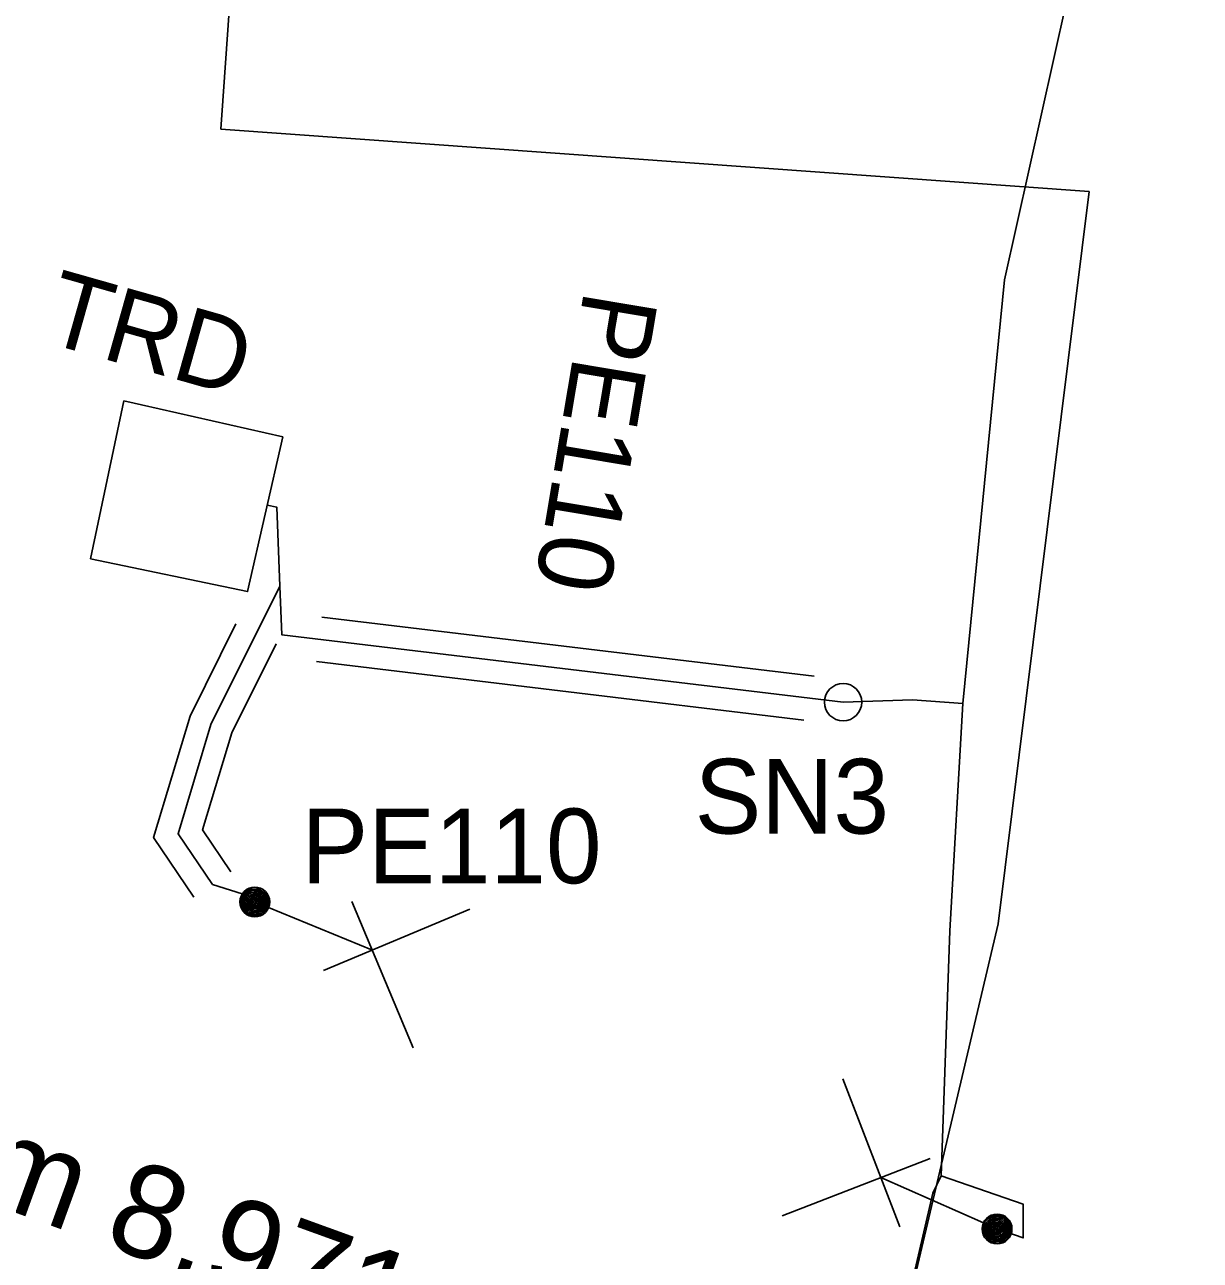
# Model space of a CAD drawing. Extents: x -731967 to -723173, y -945358 to -941505.
# Drawn here: x -725800 to -725784.27, y -942608.48 to -942591.94 of the extents above; entities that cross this region are included whole.
import ezdxf

# ---------------------------------------------------------------- set-up
doc = ezdxf.new("R2010")
doc.units = 0
for name, color, linetype in [('Vrstva 2', 7, 'Continuous'), ('Vrstva 28', 7, 'Continuous'), ('Vrstva 35', 7, 'Continuous')]:
    doc.layers.add(name, color=color, linetype=linetype)

msp = doc.modelspace()

# ---------------------------------------------------------------- linework, layer by layer
at = {"layer": 'Vrstva 2'}
for p, q in [((-725798.677, -942596.977), (-725799.12, -942599.09)), ((-725798.677, -942596.977), (-725799.12, -942599.09)), ((-725798.677, -942596.977), (-725796.55, -942597.46)), ((-725798.677, -942596.977), (-725796.55, -942597.46)), ((-725795.623, -942603.677), (-725794.804, -942605.634)), ((-725795.623, -942603.677), (-725794.804, -942605.634)), ((-725796.738, -942603.76), (-725795.35, -942604.328)), ((-725796.738, -942603.76), (-725795.35, -942604.328)), ((-725796.002, -942604.601), (-725794.045, -942603.781)), ((-725796.002, -942604.601), (-725794.045, -942603.781)), ((-725788.289, -942608.031), (-725789.054, -942606.052)), ((-725788.289, -942608.031), (-725789.054, -942606.052)), ((-725787.885, -942607.118), (-725789.864, -942607.883)), ((-725787.885, -942607.118), (-725789.864, -942607.883)), ((-725787.173, -942607.979), (-725788.545, -942607.372)), ((-725787.173, -942607.979), (-725788.545, -942607.372))]:
    msp.add_line(p, q, dxfattribs=at)
for points in [[(-725796.55, -942597.46), (-725797.02, -942599.53), (-725799.12, -942599.09)], [(-725796.55, -942597.46), (-725797.02, -942599.53), (-725799.12, -942599.09)], [(-725789.436, -942600.661), (-725796.025, -942599.872)], [(-725789.436, -942600.661), (-725796.025, -942599.872)], [(-725797.175, -942599.962), (-725797.79, -942601.199), (-725798.278, -942602.82), (-725797.738, -942603.618)], [(-725797.175, -942599.962), (-725797.79, -942601.199), (-725798.278, -942602.82), (-725797.738, -942603.618)], [(-725796.637, -942600.229), (-725797.23, -942601.421), (-725797.622, -942602.72), (-725797.242, -942603.282)], [(-725796.637, -942600.229), (-725797.23, -942601.421), (-725797.622, -942602.72), (-725797.242, -942603.282)], [(-725789.577, -942601.249), (-725796.096, -942600.468)], [(-725789.577, -942601.249), (-725796.096, -942600.468)], [(-725796.847, -942603.499), (-725796.954, -942603.49), (-725797.06, -942603.548), (-725797.11, -942603.651), (-725797.101, -942603.749), (-725797.033, -942603.838), (-725796.923, -942603.874), (-725796.825, -942603.847), (-725796.757, -942603.776), (-725796.737, -942603.664), (-725796.782, -942603.567), (-725796.859, -942603.516), (-725796.963, -942603.512), (-725797.054, -942603.572), (-725797.093, -942603.66), (-725797.08, -942603.751), (-725797.011, -942603.831), (-725796.913, -942603.855), (-725796.831, -942603.829), (-725796.768, -942603.755), (-725796.758, -942603.654), (-725796.8, -942603.574), (-725796.873, -942603.531), (-725796.97, -942603.535), (-725797.046, -942603.593), (-725797.074, -942603.667), (-725797.057, -942603.755), (-725796.989, -942603.82), (-725796.909, -942603.835), (-725796.835, -942603.807), (-725796.782, -942603.735), (-725796.779, -942603.65), (-725796.818, -942603.586), (-725796.889, -942603.548), (-725796.975, -942603.557), (-725797.033, -942603.608), (-725797.055, -942603.675), (-725797.034, -942603.754), (-725796.973, -942603.806), (-725796.907, -942603.815), (-725796.839, -942603.785), (-725796.797, -942603.719), (-725796.801, -942603.65), (-725796.835, -942603.597), (-725796.903, -942603.566), (-725796.973, -942603.579), (-725797.018, -942603.621), (-725797.036, -942603.685), (-725797.011, -942603.752), (-725796.961, -942603.79), (-725796.904, -942603.796), (-725796.845, -942603.765), (-725796.815, -942603.708), (-725796.819, -942603.653), (-725796.854, -942603.605), (-725796.913, -942603.584), (-725796.968, -942603.599), (-725797.005, -942603.635), (-725797.015, -942603.693), (-725796.992, -942603.745), (-725796.952, -942603.773), (-725796.901, -942603.774), (-725796.853, -942603.745), (-725796.833, -942603.7), (-725796.84, -942603.655), (-725796.872, -942603.616), (-725796.92, -942603.604), (-725796.96, -942603.617), (-725796.989, -942603.65), (-725796.996, -942603.698), (-725796.976, -942603.736), (-725796.943, -942603.754), (-725796.9, -942603.754), (-725796.865, -942603.728), (-725796.853, -942603.695), (-725796.859, -942603.658), (-725796.888, -942603.63), (-725796.922, -942603.624), (-725796.953, -942603.635), (-725796.973, -942603.664), (-725796.975, -942603.7), (-725796.959, -942603.723), (-725796.933, -942603.736), (-725796.901, -942603.734), (-725796.879, -942603.715), (-725796.871, -942603.69), (-725796.88, -942603.663), (-725796.901, -942603.646), (-725796.923, -942603.643), (-725796.943, -942603.652), (-725796.957, -942603.674), (-725796.956, -942603.696), (-725796.945, -942603.712), (-725796.926, -942603.718), (-725796.906, -942603.715), (-725796.896, -942603.702), (-725796.891, -942603.686), (-725796.897, -942603.671), (-725796.91, -942603.663), (-725796.922, -942603.663), (-725796.933, -942603.669)], [(-725796.847, -942603.499), (-725796.954, -942603.49), (-725797.06, -942603.548), (-725797.11, -942603.651), (-725797.101, -942603.749), (-725797.033, -942603.838), (-725796.923, -942603.874), (-725796.825, -942603.847), (-725796.757, -942603.776), (-725796.737, -942603.664), (-725796.782, -942603.567), (-725796.859, -942603.516), (-725796.963, -942603.512), (-725797.054, -942603.572), (-725797.093, -942603.66), (-725797.08, -942603.751), (-725797.011, -942603.831), (-725796.913, -942603.855), (-725796.831, -942603.829), (-725796.768, -942603.755), (-725796.758, -942603.654), (-725796.8, -942603.574), (-725796.873, -942603.531), (-725796.97, -942603.535), (-725797.046, -942603.593), (-725797.074, -942603.667), (-725797.057, -942603.755), (-725796.989, -942603.82), (-725796.909, -942603.835), (-725796.835, -942603.807), (-725796.782, -942603.735), (-725796.779, -942603.65), (-725796.818, -942603.586), (-725796.889, -942603.548), (-725796.975, -942603.557), (-725797.033, -942603.608), (-725797.055, -942603.675), (-725797.034, -942603.754), (-725796.973, -942603.806), (-725796.907, -942603.815), (-725796.839, -942603.785), (-725796.797, -942603.719), (-725796.801, -942603.65), (-725796.835, -942603.597), (-725796.903, -942603.566), (-725796.973, -942603.579), (-725797.018, -942603.621), (-725797.036, -942603.685), (-725797.011, -942603.752), (-725796.961, -942603.79), (-725796.904, -942603.796), (-725796.845, -942603.765), (-725796.815, -942603.708), (-725796.819, -942603.653), (-725796.854, -942603.605), (-725796.913, -942603.584), (-725796.968, -942603.599), (-725797.005, -942603.635), (-725797.015, -942603.693), (-725796.992, -942603.745), (-725796.952, -942603.773), (-725796.901, -942603.774), (-725796.853, -942603.745), (-725796.833, -942603.7), (-725796.84, -942603.655), (-725796.872, -942603.616), (-725796.92, -942603.604), (-725796.96, -942603.617), (-725796.989, -942603.65), (-725796.996, -942603.698), (-725796.976, -942603.736), (-725796.943, -942603.754), (-725796.9, -942603.754), (-725796.865, -942603.728), (-725796.853, -942603.695), (-725796.859, -942603.658), (-725796.888, -942603.63), (-725796.922, -942603.624), (-725796.953, -942603.635), (-725796.973, -942603.664), (-725796.975, -942603.7), (-725796.959, -942603.723), (-725796.933, -942603.736), (-725796.901, -942603.734), (-725796.879, -942603.715), (-725796.871, -942603.69), (-725796.88, -942603.663), (-725796.901, -942603.646), (-725796.923, -942603.643), (-725796.943, -942603.652), (-725796.957, -942603.674), (-725796.956, -942603.696), (-725796.945, -942603.712), (-725796.926, -942603.718), (-725796.906, -942603.715), (-725796.896, -942603.702), (-725796.891, -942603.686), (-725796.897, -942603.671), (-725796.91, -942603.663), (-725796.922, -942603.663), (-725796.933, -942603.669)], [(-725796.933, -942603.669), (-725796.938, -942603.68), (-725796.936, -942603.69), (-725796.93, -942603.698), (-725796.921, -942603.7), (-725796.913, -942603.697), (-725796.911, -942603.691), (-725796.91, -942603.685), (-725796.913, -942603.681), (-725796.917, -942603.681)], [(-725796.933, -942603.669), (-725796.938, -942603.68), (-725796.936, -942603.69), (-725796.93, -942603.698), (-725796.921, -942603.7), (-725796.913, -942603.697), (-725796.911, -942603.691), (-725796.91, -942603.685), (-725796.913, -942603.681), (-725796.917, -942603.681)], [(-725787.071, -942608.243), (-725786.965, -942608.255), (-725786.857, -942608.2), (-725786.804, -942608.099), (-725786.81, -942608), (-725786.875, -942607.91), (-725786.985, -942607.87), (-725787.084, -942607.894), (-725787.153, -942607.964), (-725787.177, -942608.075), (-725787.134, -942608.173), (-725787.058, -942608.227), (-725786.955, -942608.233), (-725786.862, -942608.176), (-725786.821, -942608.089), (-725786.831, -942607.997), (-725786.898, -942607.916), (-725786.995, -942607.889), (-725787.078, -942607.913), (-725787.143, -942607.985), (-725787.155, -942608.085), (-725787.116, -942608.166), (-725787.044, -942608.211), (-725786.947, -942608.21), (-725786.87, -942608.155), (-725786.84, -942608.082), (-725786.854, -942607.993), (-725786.92, -942607.926), (-725787, -942607.909), (-725787.075, -942607.935), (-725787.13, -942608.005), (-725787.135, -942608.09), (-725787.098, -942608.156), (-725787.028, -942608.195), (-725786.942, -942608.188), (-725786.882, -942608.14), (-725786.859, -942608.072), (-725786.877, -942607.993), (-725786.937, -942607.939), (-725787.002, -942607.929), (-725787.071, -942607.956), (-725787.115, -942608.021), (-725787.113, -942608.091), (-725787.08, -942608.145), (-725787.014, -942608.178), (-725786.943, -942608.166), (-725786.896, -942608.125), (-725786.877, -942608.062), (-725786.9, -942607.995), (-725786.949, -942607.956), (-725787.006, -942607.948), (-725787.066, -942607.977), (-725787.097, -942608.033), (-725787.094, -942608.088), (-725787.061, -942608.137), (-725787.002, -942608.16), (-725786.947, -942608.147), (-725786.91, -942608.111), (-725786.898, -942608.054), (-725786.919, -942608.001), (-725786.959, -942607.972), (-725787.01, -942607.969), (-725787.058, -942607.997), (-725787.079, -942608.041), (-725787.074, -942608.086), (-725787.043, -942608.126), (-725786.995, -942608.14), (-725786.955, -942608.128), (-725786.925, -942608.095), (-725786.917, -942608.049), (-725786.936, -942608.01), (-725786.968, -942607.991), (-725787.011, -942607.989), (-725787.046, -942608.014), (-725787.06, -942608.047), (-725787.054, -942608.084), (-725787.026, -942608.113), (-725786.993, -942608.12), (-725786.962, -942608.11), (-725786.941, -942608.082), (-725786.938, -942608.046), (-725786.953, -942608.022), (-725786.979, -942608.008), (-725787.01, -942608.009), (-725787.033, -942608.028), (-725787.041, -942608.053), (-725787.034, -942608.08), (-725787.013, -942608.098), (-725786.991, -942608.101), (-725786.971, -942608.093), (-725786.957, -942608.071), (-725786.957, -942608.049), (-725786.967, -942608.033), (-725786.986, -942608.026), (-725787.006, -942608.029), (-725787.017, -942608.042), (-725787.021, -942608.057), (-725787.016, -942608.072), (-725787.003, -942608.08), (-725786.992, -942608.081), (-725786.98, -942608.075)], [(-725787.071, -942608.243), (-725786.965, -942608.255), (-725786.857, -942608.2), (-725786.804, -942608.099), (-725786.81, -942608), (-725786.875, -942607.91), (-725786.985, -942607.87), (-725787.084, -942607.894), (-725787.153, -942607.964), (-725787.177, -942608.075), (-725787.134, -942608.173), (-725787.058, -942608.227), (-725786.955, -942608.233), (-725786.862, -942608.176), (-725786.821, -942608.089), (-725786.831, -942607.997), (-725786.898, -942607.916), (-725786.995, -942607.889), (-725787.078, -942607.913), (-725787.143, -942607.985), (-725787.155, -942608.085), (-725787.116, -942608.166), (-725787.044, -942608.211), (-725786.947, -942608.21), (-725786.87, -942608.155), (-725786.84, -942608.082), (-725786.854, -942607.993), (-725786.92, -942607.926), (-725787, -942607.909), (-725787.075, -942607.935), (-725787.13, -942608.005), (-725787.135, -942608.09), (-725787.098, -942608.156), (-725787.028, -942608.195), (-725786.942, -942608.188), (-725786.882, -942608.14), (-725786.859, -942608.072), (-725786.877, -942607.993), (-725786.937, -942607.939), (-725787.002, -942607.929), (-725787.071, -942607.956), (-725787.115, -942608.021), (-725787.113, -942608.091), (-725787.08, -942608.145), (-725787.014, -942608.178), (-725786.943, -942608.166), (-725786.896, -942608.125), (-725786.877, -942608.062), (-725786.9, -942607.995), (-725786.949, -942607.956), (-725787.006, -942607.948), (-725787.066, -942607.977), (-725787.097, -942608.033), (-725787.094, -942608.088), (-725787.061, -942608.137), (-725787.002, -942608.16), (-725786.947, -942608.147), (-725786.91, -942608.111), (-725786.898, -942608.054), (-725786.919, -942608.001), (-725786.959, -942607.972), (-725787.01, -942607.969), (-725787.058, -942607.997), (-725787.079, -942608.041), (-725787.074, -942608.086), (-725787.043, -942608.126), (-725786.995, -942608.14), (-725786.955, -942608.128), (-725786.925, -942608.095), (-725786.917, -942608.049), (-725786.936, -942608.01), (-725786.968, -942607.991), (-725787.011, -942607.989), (-725787.046, -942608.014), (-725787.06, -942608.047), (-725787.054, -942608.084), (-725787.026, -942608.113), (-725786.993, -942608.12), (-725786.962, -942608.11), (-725786.941, -942608.082), (-725786.938, -942608.046), (-725786.953, -942608.022), (-725786.979, -942608.008), (-725787.01, -942608.009), (-725787.033, -942608.028), (-725787.041, -942608.053), (-725787.034, -942608.08), (-725787.013, -942608.098), (-725786.991, -942608.101), (-725786.971, -942608.093), (-725786.957, -942608.071), (-725786.957, -942608.049), (-725786.967, -942608.033), (-725786.986, -942608.026), (-725787.006, -942608.029), (-725787.017, -942608.042), (-725787.021, -942608.057), (-725787.016, -942608.072), (-725787.003, -942608.08), (-725786.992, -942608.081), (-725786.98, -942608.075)], [(-725786.98, -942608.075), (-725786.975, -942608.064), (-725786.976, -942608.054), (-725786.983, -942608.047), (-725786.992, -942608.044), (-725787, -942608.047), (-725787.002, -942608.053), (-725787.003, -942608.059), (-725787, -942608.062), (-725786.996, -942608.063)], [(-725786.98, -942608.075), (-725786.975, -942608.064), (-725786.976, -942608.054), (-725786.983, -942608.047), (-725786.992, -942608.044), (-725787, -942608.047), (-725787.002, -942608.053), (-725787.003, -942608.059), (-725787, -942608.062), (-725786.996, -942608.063)]]:
    msp.add_lwpolyline(points, dxfattribs=at)
for centre, radius in [((-725789.05, -942601.01), 0.25), ((-725789.05, -942601.01), 0.25), ((-725796.923, -942603.684), 0.2), ((-725796.923, -942603.684), 0.2), ((-725786.99, -942608.06), 0.2), ((-725786.99, -942608.06), 0.2)]:
    msp.add_circle(centre, radius, dxfattribs=at)
at = {"layer": 'Vrstva 28'}
for points in [[(-725788.6, -942496.7), (-725787.48, -942503.69), (-725787.55, -942505.81), (-725786.31, -942516.89), (-725786.1, -942519.49), (-725785.76, -942522.98), (-725785.58, -942526.07), (-725785.3, -942533.32), (-725784.99, -942536.58), (-725784.83, -942540.71), (-725784.39, -942547.71), (-725784.27, -942553.11), (-725784.44, -942561.3), (-725784.59, -942568), (-725784.54, -942570.61), (-725784.85, -942574.82), (-725784.88, -942578.53), (-725785.17, -942583.22), (-725785.69, -942589.81), (-725785.9, -942590.91), (-725786.89, -942595.36), (-725787.45, -942601.03), (-725788.12, -942600.98)], [(-725788.6, -942496.7), (-725787.48, -942503.69), (-725787.55, -942505.81), (-725786.31, -942516.89), (-725786.1, -942519.49), (-725785.76, -942522.98), (-725785.58, -942526.07), (-725785.3, -942533.32), (-725784.99, -942536.58), (-725784.83, -942540.71), (-725784.39, -942547.71), (-725784.27, -942553.11), (-725784.44, -942561.3), (-725784.59, -942568), (-725784.54, -942570.61), (-725784.85, -942574.82), (-725784.88, -942578.53), (-725785.17, -942583.22), (-725785.69, -942589.81), (-725785.9, -942590.91), (-725786.89, -942595.36), (-725787.45, -942601.03), (-725788.12, -942600.98)], [(-725796.758, -942598.375), (-725796.63, -942598.4), (-725796.59, -942599.46), (-725797.51, -942601.31), (-725797.95, -942602.77), (-725797.49, -942603.45)], [(-725796.758, -942598.375), (-725796.63, -942598.4), (-725796.59, -942599.46), (-725797.51, -942601.31), (-725797.95, -942602.77), (-725797.49, -942603.45)], [(-725788.12, -942600.98), (-725789.05, -942601.01), (-725796.56, -942600.11), (-725796.59, -942599.46)], [(-725788.12, -942600.98), (-725789.05, -942601.01), (-725796.56, -942600.11), (-725796.59, -942599.46)], [(-725786.99, -942608.06), (-725786.64, -942608.18), (-725786.64, -942607.73), (-725787.74, -942607.35), (-725787.62, -942604.07), (-725787.45, -942601.03)], [(-725786.99, -942608.06), (-725786.64, -942608.18), (-725786.64, -942607.73), (-725787.74, -942607.35), (-725787.62, -942604.07), (-725787.45, -942601.03)], [(-725797.49, -942603.45), (-725796.85, -942603.65)], [(-725797.49, -942603.45), (-725796.85, -942603.65)], [(-725787.74, -942607.35), (-725787.85, -942607.58), (-725790.42, -942618.63)], [(-725787.74, -942607.35), (-725787.85, -942607.58), (-725790.42, -942618.63)]]:
    msp.add_lwpolyline(points, dxfattribs=at)
at = {"layer": 'Vrstva 35'}
for p, q in [((-725796.914, -942586.871), (-725797.38, -942593.34)), ((-725797.38, -942593.34), (-725785.758, -942594.176)), ((-725785.758, -942594.176), (-725786.975, -942603.978)), ((-725786.975, -942603.978), (-725791.571, -942623.436))]:
    msp.add_line(p, q, dxfattribs=at)

# ---------------------------------------------------------------- texts
at = {"layer": 'Vrstva 2'}
for s, rotation, p in [('TRD', 344.1772, (-725799.786, -942596.178)), ('TRD', 344.1772, (-725799.786, -942596.178)), ('PE110', 260.4691, (-725792.512, -942595.477)), ('PE110', 260.4691, (-725792.512, -942595.477))]:
    msp.add_text(s, height=1, rotation=rotation, dxfattribs=at).set_placement(p)
for s, p in [('SN3', (-725791.037, -942602.769)), ('SN3', (-725791.037, -942602.769)), ('PE110', (-725796.298, -942603.434)), ('PE110', (-725796.298, -942603.434))]:
    msp.add_text(s, height=1, dxfattribs=at).set_placement(p)
at = {"layer": 'Vrstva 28'}
msp.add_text('P3540, km 8,971', height=1.24131, rotation=340.0711, dxfattribs=at).set_placement((-725806.874, -942605.396))

doc.saveas('drawing.dxf')
